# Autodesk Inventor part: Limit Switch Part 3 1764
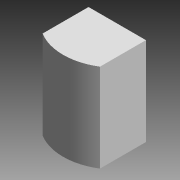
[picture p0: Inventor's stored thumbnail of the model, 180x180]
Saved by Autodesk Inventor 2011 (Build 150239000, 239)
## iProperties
Shininess: 0.0
Created: 2002-01
Part Number: Limit Switch Part 3 1764
Document SubType Name: Modeling
Density: 1 g/cm^3
Density: 0.0
Volumn: 0.0
Area: 0.0
PropertySet Name: Model Information
Control State: 0
Master: False
Checked Out: False
Author: Administrator
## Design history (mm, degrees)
node "Base1"
body "Solid1"
